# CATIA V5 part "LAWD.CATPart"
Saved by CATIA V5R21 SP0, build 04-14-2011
Part number: LAWD.SLDPRT
Bounding box of the stored display mesh (mm): x -1.85 to 1.85, y -1.75 to 1.75, z -0.25 to 0.5
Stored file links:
  C:\Users\user\Desktop\CATIA文件\0-最新文件\LAWD\LAWD.CATPart
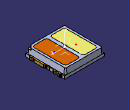
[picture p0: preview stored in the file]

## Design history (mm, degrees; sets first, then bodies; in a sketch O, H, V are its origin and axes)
AxisSystem1: origin (0, 0, 0.5), X (1, 0, 0), Y (0, 1, 0), Z (0, 0, 1)
Set1
  DatumSurface1 to DatumSurface36
  Line1 to Line10: stored without definition
  Circle1: stored without definition
  Circle2: stored without definition
  Line11 to Line17: stored without definition
  Circle3: stored without definition
  Circle4: stored without definition
  Line18: stored without definition
  Line19: stored without definition
  Circle5: stored without definition
  Circle6: stored without definition
  Line20 to Line23: stored without definition
  Circle7: stored without definition
  Circle8: stored without definition
  Line24: stored without definition
  Circle9: stored without definition
  Line25 to Line28: stored without definition
  Circle10: stored without definition
  Line29: stored without definition
  Circle11: stored without definition
  Circle12: stored without definition
  Line30: stored without definition
  Circle13: stored without definition
  Circle14: stored without definition
  Line31: stored without definition
  Circle15: stored without definition
  Circle16: stored without definition
  Line32 to Line37: stored without definition
  Circle17: stored without definition
  Circle18: stored without definition
  Line38: stored without definition
  Circle19: stored without definition
  Line39: stored without definition
  Line40: stored without definition
  Circle20: stored without definition
  Line41 to Line44: stored without definition
  Circle21: stored without definition
  Line45 to Line60: stored without definition
  Circle22: stored without definition
  Line61: stored without definition
  Circle23: stored without definition
  Line62 to Line64: stored without definition
  Circle24: stored without definition
  Line65: stored without definition
  Line66: stored without definition
  Circle25: stored without definition
  Line67 to Line69: stored without definition
  Circle26: stored without definition
  Circle27: stored without definition
  Line70 to Line72: stored without definition
  Circle28: stored without definition
  Line73: stored without definition
  DatumSurface37 to DatumSurface72
  Line74: stored without definition
  Line75: stored without definition
  Circle29: stored without definition
  Circle30: stored without definition
  Line76: stored without definition
  Line77: stored without definition
  Circle31: stored without definition
  Line78 to Line84: stored without definition
  Circle32: stored without definition
  Circle33: stored without definition
  Line85: stored without definition
  Circle34: stored without definition
  Line86 to Line92: stored without definition
  Circle35: stored without definition
  Line93 to Line97: stored without definition
  Circle36: stored without definition
  Line98: stored without definition
  Line99: stored without definition
  Circle37: stored without definition
  Line100 to Line114: stored without definition
  Circle38 to Circle41: stored without definition
  Line115 to Line118: stored without definition
  Circle42: stored without definition
  Circle43: stored without definition
  Line119: stored without definition
  Line120: stored without definition
  Circle44: stored without definition
  Circle45: stored without definition
  Line121 to Line124: stored without definition
  Circle46: stored without definition
  Circle47: stored without definition
  Line125: stored without definition
  Circle48: stored without definition
  Circle49: stored without definition
  Line126 to Line140: stored without definition
  Circle50: stored without definition
  Circle51: stored without definition
  Line141 to Line144: stored without definition
  Circle52: stored without definition
  Line145: stored without definition
  Line146: stored without definition
  Circle53 to Circle56: stored without definition
  DatumSurface73 to DatumSurface105
  Line147 to Line150: stored without definition
  Circle57: stored without definition
  Line151: stored without definition
  Line152: stored without definition
  Circle58: stored without definition
  Circle59: stored without definition
  Line153: stored without definition
  Line154: stored without definition
  Circle60: stored without definition
  Line155: stored without definition
  Circle61: stored without definition
  Circle62: stored without definition
  Line156 to Line162: stored without definition
  Circle63: stored without definition
  Circle64: stored without definition
  Line163 to Line167: stored without definition
  Circle65: stored without definition
  Line168 to Line176: stored without definition
  Circle66: stored without definition
  Line177: stored without definition
  Line178: stored without definition
  Circle67: stored without definition
  Line179: stored without definition
  Circle68: stored without definition
  Line180: stored without definition
  Line181: stored without definition
  Circle69: stored without definition
  Line182: stored without definition
  Line183: stored without definition
  Circle70: stored without definition
  Line184: stored without definition
  Circle71: stored without definition
  Circle72: stored without definition
  Line185 to Line191: stored without definition
  Circle73: stored without definition
  Line192 to Line197: stored without definition
  Circle74: stored without definition
  Line198 to Line200: stored without definition
  Circle75: stored without definition
  Line201 to Line204: stored without definition
  Circle76: stored without definition
  Line205 to Line218: stored without definition
  DatumSurface106 to DatumSurface138
  Line219 to Line222: stored without definition
  Circle77: stored without definition
  Line223: stored without definition
  Line224: stored without definition
  Circle78: stored without definition
  Circle79: stored without definition
  Line225: stored without definition
  Line226: stored without definition
  Circle80: stored without definition
  Line227: stored without definition
  Circle81: stored without definition
  Circle82: stored without definition
  Line228 to Line234: stored without definition
  Circle83: stored without definition
  Circle84: stored without definition
  Line235 to Line239: stored without definition
  Circle85: stored without definition
  Line240 to Line249: stored without definition
  Circle86: stored without definition
  Line250: stored without definition
  Line251: stored without definition
  Circle87: stored without definition
  Line252: stored without definition
  Circle88: stored without definition
  Line253: stored without definition
  Line254: stored without definition
  Circle89: stored without definition
  Line255: stored without definition
  Line256: stored without definition
  Circle90: stored without definition
  Line257: stored without definition
  Circle91: stored without definition
  Circle92: stored without definition
  Line258 to Line265: stored without definition
  Circle93: stored without definition
  Line266 to Line271: stored without definition
  Circle94: stored without definition
  Line272 to Line274: stored without definition
  Circle95: stored without definition
  Line275 to Line278: stored without definition
  Circle96: stored without definition
  Line279 to Line290: stored without definition
  DatumSurface139 to DatumSurface260
  DatumCurve1
  Line291: stored without definition
  DatumCurve2
  Line292: stored without definition
  DatumCurve3
  Line293: stored without definition
  DatumCurve4
  Line294 to Line297: stored without definition
  Circle97: stored without definition
  Line298 to Line304: stored without definition
  Circle98: stored without definition
  Line305 to Line322: stored without definition
  Circle99: stored without definition
  Line323: stored without definition
  Circle100: stored without definition
  Line324 to Line329: stored without definition
  Circle101: stored without definition
  Line330: stored without definition
  Circle102: stored without definition
  Circle103: stored without definition
  Line331: stored without definition
  Circle104: stored without definition
  Line332 to Line337: stored without definition
  Circle105: stored without definition
  Circle106: stored without definition
  Line338: stored without definition
  Circle107: stored without definition
  Circle108: stored without definition
  Line339 to Line342: stored without definition
  Circle109: stored without definition
  Circle110: stored without definition
  Line343 to Line356: stored without definition
  Circle111: stored without definition
  Line357: stored without definition
  Line358: stored without definition
  Circle112: stored without definition
  Circle113: stored without definition
  Line359: stored without definition
  Line360: stored without definition
  Circle114: stored without definition
  Line361: stored without definition
  Circle115: stored without definition
  Circle116: stored without definition
  Line362 to Line367: stored without definition
  Circle117: stored without definition
  Circle118: stored without definition
  Line368 to Line372: stored without definition
  Circle119: stored without definition
  Line373 to Line380: stored without definition
  Circle120: stored without definition
  Line381 to Line383: stored without definition
  Circle121: stored without definition
  Line384: stored without definition
  Line385: stored without definition
  Circle122: stored without definition
  Line386 to Line398: stored without definition
  Circle123: stored without definition
  Line399: stored without definition
  Line400: stored without definition
  Circle124: stored without definition
  Circle125: stored without definition
  Line401: stored without definition
  Line402: stored without definition
  Circle126: stored without definition
  Line403: stored without definition
  Circle127: stored without definition
  Circle128: stored without definition
  Line404 to Line409: stored without definition
  Circle129: stored without definition
  Circle130: stored without definition
  Line410 to Line414: stored without definition
  Circle131: stored without definition
  Line415 to Line422: stored without definition
  Circle132: stored without definition
  Line423 to Line425: stored without definition
  Circle133: stored without definition
  Line426: stored without definition
  Line427: stored without definition
  Circle134: stored without definition
  Line428 to Line435: stored without definition
  Circle135: stored without definition
  Line436: stored without definition
  Line437: stored without definition
  Circle136: stored without definition
  Circle137: stored without definition
  Line438: stored without definition
  Line439: stored without definition
  Circle138: stored without definition
  Line440 to Line446: stored without definition
  Circle139: stored without definition
  Circle140: stored without definition
  Line447 to Line454: stored without definition
  Circle141: stored without definition
  Line455 to Line459: stored without definition
  Circle142: stored without definition
  Line460: stored without definition
  Line461: stored without definition
  Circle143: stored without definition
  Line462 to Line473: stored without definition
  Circle144: stored without definition
  Circle145: stored without definition
  Line474 to Line477: stored without definition
  Circle146: stored without definition
  Line478 to Line489: stored without definition
  Circle147: stored without definition
  Circle148: stored without definition
  Line490 to Line503: stored without definition
  Circle149: stored without definition
  Circle150: stored without definition
  Line504 to Line516: stored without definition
  Circle151: stored without definition
  Line517: stored without definition
  Circle152: stored without definition
  Line518 to Line528: stored without definition
  Circle153: stored without definition
  Circle154: stored without definition
  Line529 to Line542: stored without definition
  Circle155: stored without definition
  Line543: stored without definition
  Line544: stored without definition
  Circle156: stored without definition
  Line545: stored without definition
  Circle157: stored without definition
  Line546 to Line549: stored without definition
  Circle158: stored without definition
  Line550 to Line555: stored without definition
  Circle159: stored without definition
  Line556 to Line560: stored without definition
  Circle160: stored without definition
  DatumCurve5
  Line561: stored without definition
  DatumCurve6
  Line562: stored without definition
  DatumCurve7
  Line563: stored without definition
  DatumCurve8
  Line564: stored without definition
  DatumCurve9
  Line565: stored without definition
  DatumCurve10
  Line566: stored without definition
  DatumCurve11
  Line567: stored without definition
  DatumCurve12
  Line568: stored without definition
  DatumCurve13
  Line569: stored without definition
  DatumCurve14
  Line570: stored without definition
  DatumCurve15
  Line571: stored without definition
  DatumCurve16
  Line572: stored without definition
  DatumCurve17
  Line573: stored without definition
  DatumCurve18
  Line574: stored without definition
  DatumCurve19
  Line575: stored without definition
  DatumCurve20
  Line576: stored without definition
  Point1 "几何中心&发光中心（测试原点）": type Between, FirstPoint vertex [face of DatumSurface256], SecondPoint vertex [face of DatumSurface256], Ratio 0.5
  Point2 "白光虚拟坐标": (-0.7792, 0.2095, -0.1244), relative to Point1, in AxisSystem1
  Point3 "琥珀光虚拟坐标": (0.7862, -0.2034, -0.1002), relative to Point1, in AxisSystem1
Body1 (main body)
